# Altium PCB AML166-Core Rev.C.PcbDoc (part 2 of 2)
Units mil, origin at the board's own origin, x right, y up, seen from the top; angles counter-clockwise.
Board outline 3307.09 x 2047.24 mil, 4 copper layers (Top Layer, L2, L3, Bottom Layer), stack 30.634 mil thick; 138 components, 74 nets, 392 pads, 430 vias.
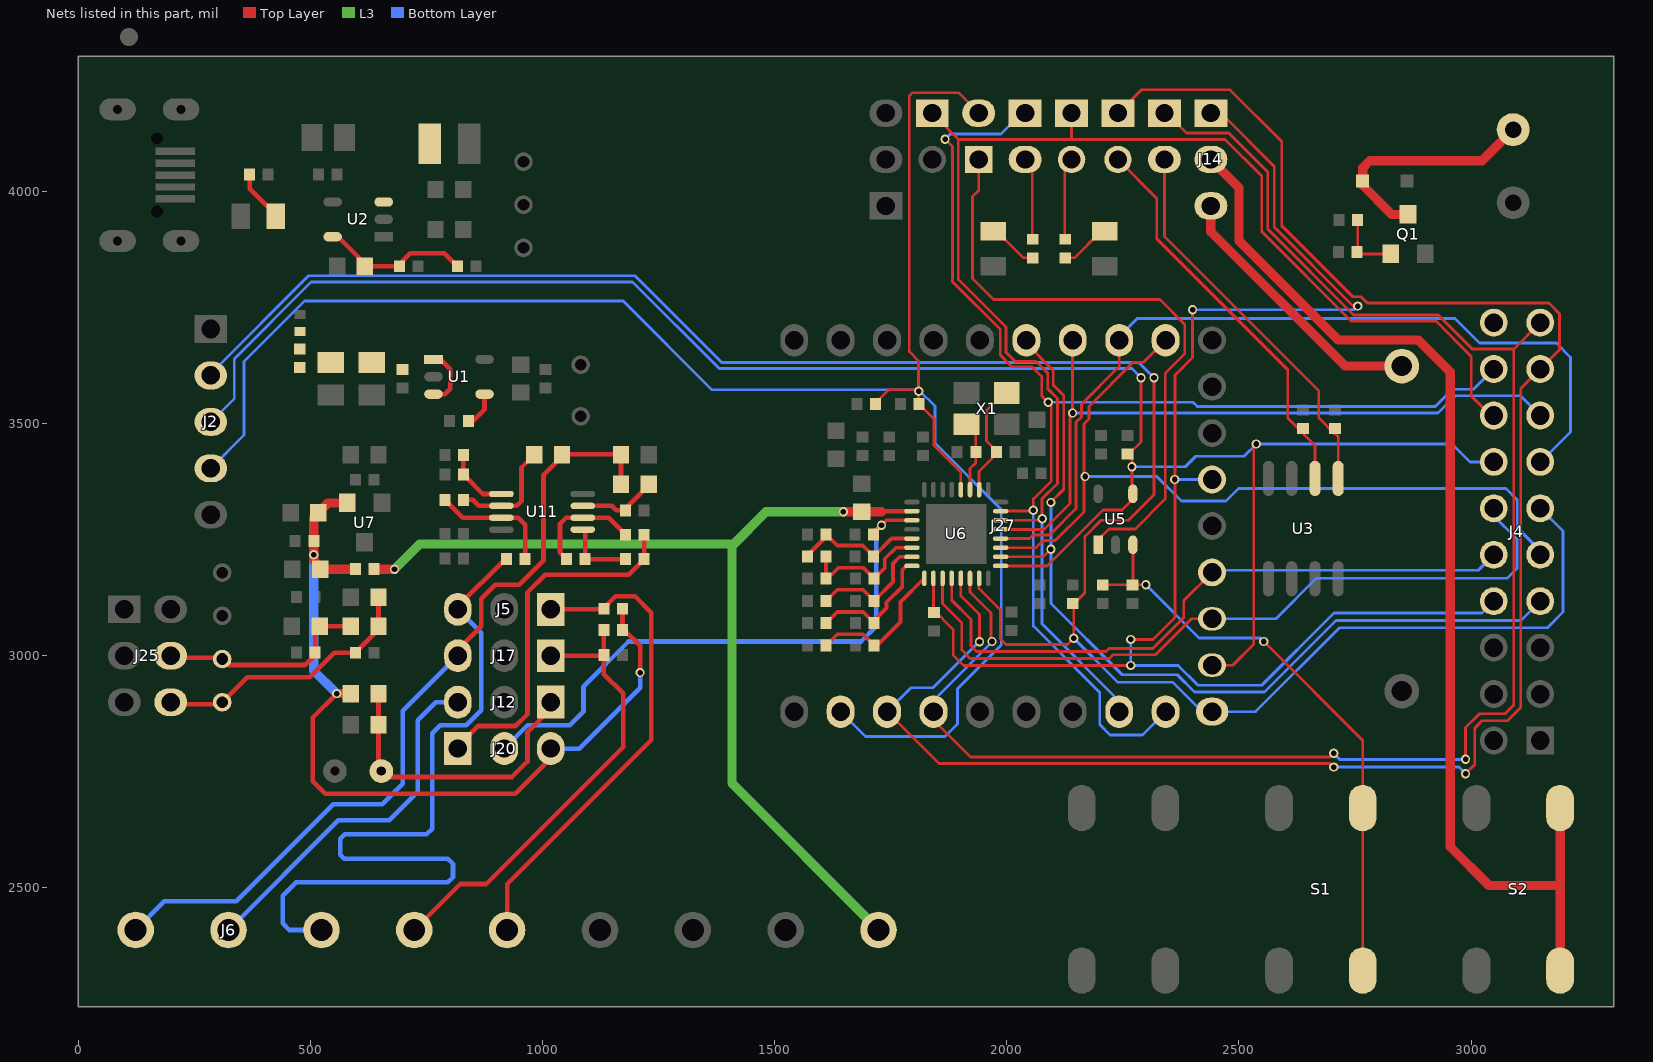
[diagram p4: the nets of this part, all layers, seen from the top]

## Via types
v1: diameter 20, hole 12, Top Layer to Bottom Layer, tented both sides, 430 vias

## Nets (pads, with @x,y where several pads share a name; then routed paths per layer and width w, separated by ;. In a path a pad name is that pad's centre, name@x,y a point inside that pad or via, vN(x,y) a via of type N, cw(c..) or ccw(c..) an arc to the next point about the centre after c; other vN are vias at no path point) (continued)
CALI_1: C41.2 Cali7.1 J25.4 R37.2 R38.2 | length 455.1
  Top Layer w10: J25.4@180,2993.11 J25.4@180,3001 ; J25.4@199,2996 306.98,2996 Cali7.1@309.87,2993.11 ; Cali7.1@322.63,2980.37 488.75,2980.37 510,3001.62 C41.2@510,3007.37 510,3064 R38.2@520,3064 R37.2@586.57,3064
CALI_2: C42.2 Cali8.1 J25.6 R33.1 R37.1 | length 582
  Top Layer w10: J25.6@199,2896 305.87,2896 Cali8.1@309.87,2900 ; Cali8.1@309.87,2901 310.87,2901 363.87,2954 498.27,2954 551,3006.73 C42.2@596.57,3006.73 R37.1@650.2,3060.36 ; R37.1@646.57,3064 R33.1@646.57,3126.37 ; R37.1@652,3059.14 R37.1@652.57,3059.71
CS/GPIO7_MINIP: J4.7 J27.22 U6.26 | length 1939.9
  Top Layer w6: U6.26@1986.56,3213.3 2078,3213.3 v1@2095,3230.3 ; J27.22@2041.98,3679.79 2041.98,3673.02 2100,3615 2100,3583.42 2122.6,3560.83 2122.6,3358.94 v1@2095,3331.34
  Bottom Layer w6: v1(2095,3330.41) v1(2095,3229.3) 2095,3113 2248.66,2959.34 2367,2959.34 2404,2922.34 2554.94,2922.34 2708.94,3076.34 3107.44,3076.34 J4.7@3148.82,3117.72
DAC/IO21_MICROP: J4.8 J14.1 J27.15 R8.2 U6.18 | length 3293.7
  Top Layer w6: U6.18@1841.87,3167.04 1841.87,3099.66 1884.41,3057.12 1884.41,3001.93 1907,2979.34 v1@2261,2979.34 ; v1(2267,3035.34) 2315,3035.34 2362,3082.34 2362,3604.44 2400,3642.44 v1@2400,3739.34 ; J14.1@2439.37,4169.09 2461,4169.09 2576,4054.09 2576,3923.34 2746,3753.34 v1(2756,3753.34)
  Bottom Layer w6: v1(2267,3035.34) v1(2267,2979.34) 2369,2979.34 2411.76,2936.58 2549.04,2936.58 2704.8,3092.34 3023.44,3092.34 J4.8@3048.82,3117.72 ; v1@2362,3379.79 J27.15@2441.98,3379.79 ; v1@2400,3739.34 2406,3745.34 2748,3745.34 v1(2756,3753.34)
  other v1: 2361.7,3379.79 2400,3745.34
GPIO11_MINIP: J2.2 J4.11 J27.10 R11.1 U6.23 | length 4649.7
  Top Layer w6: U6.23@1940.3,3167.04 1939.69,3166.43 1939.69,3145.31 1986,3099 1986,3036.59 1998.25,3024.34 2130.34,3024.34 v1(2144,3038) 2144,3112 2168,3136 2168,3257.34 2202.66,3292 2262,3292 2317,3347 v1(2317,3598.94)
  Bottom Layer w6: J2.2@290.02,3604.34 290.02,3612.59 496.07,3818.63 1199.13,3818.63 1386.02,3631.75 2284.19,3631.75 v1(2317,3598.94) ; v1(2144,3038) 2238.66,2943.34 2356.76,2943.34 2420.3,2879.79 J27.10@2441.98,2879.79 2535.4,2879.79 2715.94,3060.34 3164,3060.34 3198,3094.34 3198,3268.54 J4.11@3148.82,3317.72
GPIO14_MINIP: J2.3 J4.14 J27.11 R12.2 U5.4 U6.25 | length 4253.2
  Top Layer w6: U6.25@1986.56,3193.61 2086.28,3193.61 2207,3314.34 2248.34,3314.34 2269.49,3335.49 v1(2269.49,3407.34) R12.2@2269.49,3441.43 ; R12.2@2260,3435.02 2263.08,3435.02 R12.2@2269.49,3441.43 ; R12.2@2266,3439 2269.49,3442.49 R12.2@2269.49,3441.43 ; v1(2289,3598.94) 2289,3460.94 R12.2@2269.49,3441.43 ; J27.11@2441.98,2979.79 2486.46,2979.79 2532,3025.34 2532,3450.94 v1(2537.4,3456.34)
  Bottom Layer w6: J2.3@285.43,3503.94 336,3554.5 336,3640 501.5,3805.5 1193.69,3805.5 1380.58,3618.62 2269.32,3618.62 v1(2289,3598.94) ; v1(2269.49,3407.34) 2384.34,3407.34 2407,3430 2511.06,3430 v1(2537.4,3456.34) 2959,3456.34 2997.62,3417.72 J4.14@3048.82,3417.72
GPIO16_MINIP: J4.16 J7.1 J10.1 J27.8 U6.30 | length 3150.2
  Top Layer w6: J7.1@1842.81,4165.66 1842.81,4164.99 1895.46,4112.34 ; U6.30@1986.56,3292.04 2076,3292.04 v1(2076,3295.04) 2076,3338.37 2109,3371.37 2109,3554.34 2088,3575.34 2088,3609 2063,3634 2018,3634 1998,3654 1998,3708 1895.46,3810.54 1895.46,4112.34 ; 2139.37,4112.97 J10.1@2139.37,4169.09 ; J4.16@3049.41,3510.85 3000.39,3559.87 3000.39,3644.94 2924.24,3721.09 2741.66,3721.09 2549,3913.75 2549,4033.34 2470,4112.34 1895.46,4112.34
  Bottom Layer w6: v1@2076,3292.04 2076,3069.06 J27.8@2241.98,2903.08
GPIO18_MINIP: J4.18 J9.1 J27.9 U6.31 | length 2887.4
  Top Layer w6: v1(1867,4112.97) 1883,4096.97 1883,3805.73 1986,3702.73 1986,3647.45 2010.95,3622.5 2054.21,3622.5 2075,3601.71 2075,3560.34 v1(2089,3546.34) 2095.81,3539.53 2095.81,3376.96 2057,3338.15 v1(2057,3313.72) 2057,3311.72 U6.31@1986.56,3311.72
  Bottom Layer w6: v1(1867,4112.97) 1878.03,4124 1987.46,4124 2032.55,4169.09 J9.1@2039.37,4169.09 ; v1@2057,3311.72 2057,3064.06 2200,2921.06 2200,2852 2222.21,2829.79 2291.98,2829.79 J27.9@2341.98,2879.79 ; v1@2093,3546.34 2401,3546.34 2410.24,3537.09 2922.76,3537.09 2960,3574.34 3005.44,3574.34 J4.18@3048.82,3617.72
GPIO20_MINIP: J4.20
LED0: J9.2 R3.2 | length 155.2
  Top Layer w6: R3.2@2054.6,3898.7 J9.2@2054.6,4053.86
LED1: J10.2 R4.2 | length 155.6
  Top Layer w6: R4.2@2124.6,3898.7 J10.2@2124.6,4054.33
LM75_SCL: J4.17 J11.1 J27.3 U6.21 | length 4107.2
  Top Layer w6: J27.3@1741.98,2879.79 1853.77,2768 2696.34,2768 v1(2704,2760.34) ; U6.21@1900.93,3167.04 1900.93,3129.07 1941.08,3088.92 v1(1941.08,3030.08) ; J11.1@2246.24,4169.09 J11.1@2239.37,4169.09 2289.37,4219.09 2480.77,4219.09 2592,4107.86 2592,3926.34 2745,3773.34 2762.87,3773.34 2776.36,3759.85 3167.41,3759.85 3190.31,3736.95 3190.31,3659.21 J4.17@3148.82,3617.72 3107,3575.9 3107,2888.34 3079,2860.34 3024,2860.34 3007.71,2844.05 3007.71,2766 v1(2988,2746.29)
  Bottom Layer w6: J27.3@1741.98,2879.79 1793.52,2931.34 1841.15,2931.34 v1@1940.49,3030.67 ; v1(2704,2760.34) 2973.95,2760.34 v1(2988,2746.29)
LM75_SDA: J4.19 J13.1 J27.4 U6.22 | length 3637.8
  Top Layer w6: J27.4@1841.98,2879.79 1841.98,2861.55 1921.53,2782 2695.91,2782 v1(2704,2790.09) ; U6.22@1920.61,3167.04 1920.61,3137.41 1966.09,3091.93 v1@1966.09,3032.91 ; J13.1@2339.37,4169.09 2344.24,4169.09 2387,4126.34 2478,4126.34 2562,4042.34 2562,3919.14 2747.04,3734.09 2929.24,3734.09 3002.44,3660.9 3092,3660.9 ; v1(2988,2776.98) 2988,2845.55 3017.79,2875.34 3072.79,2875.34 3092,2894.55 3092,3660.9 ; J4.19@3148.82,3717.72 3092,3660.9
  Bottom Layer w6: J27.4@1841.98,2879.79 1841.98,2903.98 1963.67,3025.67 v1@1971.33,3025.67 ; v1(2704,2790.09) 2717.12,2776.98 v1(2988,2776.98)
  other v1: 1968,3030.84
MISO/GPIO9_MINIP: J4.9 J27.19 U6.27 | length 1775
  Top Layer w6: U6.27@1986.56,3232.98 2062.98,3232.98 2078.3,3248.3 2104.3,3248.3 2166,3310 v1@2166,3385.83 ; v1@2166,3390.84 2166,3499.14 2177,3510.14 2177,3537.34 2272,3632.34 2294.52,3632.34 J27.19@2341.98,3679.79
  Bottom Layer w6: v1(2168.5,3386.34) 2323,3386.34 2376,3333.34 2472,3333.34 2499,3360.34 3075,3360.34 3099.41,3335.93 3099.41,3275.85 3148.82,3226.44 J4.9@3148.82,3217.72
MISO/IO11_MICROP: J4.13 J27.20 U6.28 | length 1873.8
  Top Layer w6: U6.28@1986.56,3252.67 2048.76,3252.67 2056.45,3260.35 2092.35,3260.35 2149,3317 2149,3503.17 2160.6,3514.77 2160.6,3541.94 2241.98,3623.31 J27.20@2241.98,3679.79
  Bottom Layer w6: J27.20@2241.98,3679.79 2241.98,3687.31 2281,3726.34 2965.23,3726.34 3018.02,3673.55 3183.71,3673.55 3214.31,3642.95 3214.31,3482.35 3149.68,3417.72 J4.13@3148.82,3417.72
MOSI/GPIO15_MINIP: J4.15 J27.21 U6.29 | length 1565.1
  Top Layer w6: U6.29@1986.56,3272.35 2080.26,3272.35 2136,3328.09 2136,3517.49 v1(2141.6,3523.09) J27.21@2141.6,3673.81 ; J27.21@2139,3676.82 J27.21@2142.01,3673.81
  Bottom Layer w6: v1(2141.6,3523.09) 2928.56,3523.09 2965.8,3560.34 3106.2,3560.34 J4.15@3148.82,3517.72
NetBZ1_1: BZ1.1 D1.2 Q1.3 | length 519.2
  Top Layer w20: Q1.3@2864.09,3950.84 2829.12,3950.84 2766.59,4013.38 D1.2@2766.59,4022.84 2766.59,4050.95 2781.98,4066.34 3023.35,4066.34 BZ1.1@3090.55,4133.54
NetC3_1: C3.1 U1.4 | length 68.3
  Top Layer w10: C3.1@850,3505.71 875,3530.71 U1.4@875,3563.67
NetC6_1: C6.1 C15.1 C43.1 R16.2 U1.1 U1.3 | length 127.6
  Top Layer w10: U1.3@765,3563.67 789.3,3563.67 801,3575.37 801,3617.37 779.9,3638.47 U1.1@765,3638.47
NetC8_2: C8.2 R10.1 R13.2 U2.5 | length 321.2
  Top Layer w10: U2.5@547.81,3902.78 U2.5@559.07,3902.78 ; U2.5@559.37,3903.08 617.31,3845.14 R13.2@617.31,3839.18 687.18,3839.18 715,3867 788.49,3867 R10.1@816.31,3839.18
NetC9_1: C9.1 C10.1 R14.2 U6.13 | length 282
  Top Layer w8: R14.2@1610.69,3257.02 R14.2@1610.69,3261.68 1634.81,3237.56 1689.46,3237.56 C9.1@1713.09,3213.93 1751.82,3252.67 U6.13@1795.61,3252.67
  Top Layer w10: C10.1@1570.69,3217.02 R14.2@1610.69,3257.02
NetC10_2: C10.2 C11.1 R17.2 U6.14 | length 291.7
  Top Layer w8: C10.2@1610.69,3213.93 R17.2@1610.69,3166.18 1614.18,3166.18 1638,3190 1690.27,3190 C11.1@1714.09,3166.18 1737,3189.1 1737,3209 1760.98,3232.98 U6.14@1795.61,3232.98
NetC12_1: C12.1 R27.2 U6.15 | length 267.3
  Top Layer w8: R27.2@1610.69,3118.43 1634.59,3142.34 1690.34,3142.34 C12.1@1714.24,3118.43 1755,3159.19 1755,3199 1769.3,3213.3 U6.15@1795.61,3213.3
NetC21_1: C21.1 R18.2 S1.2 S1.3 U5.3 | length 1280.8
  Top Layer w6: R18.2@2206.5,3153.02 C21.1@2271,3153.02 ; U5.3@2271.49,3239.02 2271.49,3153.51 C21.1@2271,3153.02 ; v1(2299.51,3153.02) C21.1@2271,3153.02 ; v1(2553.5,3030.84) 2766.52,2817.82 S1.3@2766.52,2672.09 S1.2@2766.52,2322.09
  Bottom Layer w6: v1(2299.51,3153.02) 2414.2,3038.34 2546,3038.34 v1(2553.5,3030.84)
NetC24_1: C24.1 R28.2 U6.16 | length 287.3
  Top Layer w8: R28.2@1610.69,3070.39 1634.64,3094.34 1690.59,3094.34 C24.1@1714.24,3070.68 1714.24,3076.25 1741,3103 1741,3115.3 1775,3149.3 1775,3185.53 1783.08,3193.61 U6.16@1795.61,3193.61
NetC27_1: C27.1 R24.2 U11.6 | length 245.7
  Top Layer w10: C27.1@829.37,3335.91 850.02,3335.91 862.86,3323.07 U11.6@911.34,3323.07 944.38,3323.07 954.62,3333.31 954.62,3405.73 R24.2@981.85,3432.96
NetC27_2: C27.2 R25.1 U11.7 | length 269.4
  Top Layer w10: C27.2@789.37,3335.91 827.81,3297.48 U11.7@911.34,3297.48 947.45,3297.48 962.35,3282.58 R25.1@962.35,3208.27
NetC32_1: C32.1 R29.2 U6.17 | length 316.4
  Top Layer w8: R29.2@1610.69,3022.34 1634.68,3046.34 1690.24,3046.34 C32.1@1714.24,3022.34 1720.34,3022.34 1771,3073 1771,3115.85 U6.17@1822.19,3167.04
NetC36_1: C36.1 R30.2 U11.3 | length 173.2
  Top Layer w10: U11.3@1086.54,3323.07 1148.83,3323.07 1158.62,3313.27 C36.1@1178.94,3313.27 1178.94,3317.6 1228.94,3367.6 R30.2@1228.94,3369.27
NetC39_1: C39.1 R50.2 U11.2 | length 244.1
  Top Layer w10: C39.1@1051.76,3208.27 1037.62,3222.41 1037.62,3284.68 1050.42,3297.48 U11.2@1086.54,3297.48 1142.23,3297.48 R50.2@1178.94,3260.77
NetC39_2: C39.2 R48.1 U11.1 | length 153
  Top Layer w10: U11.1@1086.54,3271.89 1091.76,3266.66 C39.2@1091.76,3208.27 R48.1@1178.94,3208.27
NetJ14_2: J14.2 S2.2 S2.3 | length 2424.4
  Top Layer w20: J14.2@2439.37,4060.51 J14.2@2439.37,4069.09 2500,4008.46 2500,3894.34 2714,3680.34 2886,3680.34 2955,3611.34 2955,2589 3038.66,2505.34 3191.69,2505.34 ; S2.2@3191.69,2322.09 3191.69,2505.34 ; S2.3@3191.69,2672.09 3191.69,2505.34
NetJ14_3: J14.3 R7.2 | length 586.7
  Top Layer w20: J14.3@2439.37,3969.09 2439.37,3913.61 2728.89,3624.09 R7.2@2850.63,3624.09
NetL1_1: L1.1 U2.3
NetL2_1: L2.1 R16.1
NetLED0_2: LED0.2 R3.1 | length 109.4
  Top Layer w6: LED0.2@1970.63,3914.97 LED0.2@1978.03,3914.97 ; LED0.2@1978.41,3914.97 LED0.2@1978.03,3914.97 ; R3.1@2055.71,3857.29 2035.71,3857.29 LED0.2@1978.03,3914.97
NetLED1_2: LED1.2 R4.1 | length 108.9
  Top Layer w6: R4.1@2125.71,3857.29 2145.7,3857.29 2203.38,3914.97 LED1.2@2210.71,3914.97
NetLED3_1: LED3.1 R9.1 | length 112.8
  Top Layer w10: R9.1@369,4036.37 369,4006.34 425.68,3949.66 LED3.1@425.68,3947
NetQ1_1: Q1.1 R1.1 R2.2 | length 141
  Top Layer w6: R2.2@2755.69,3938.82 2755.69,3871.01 2760.85,3865.84 Q1.1@2826.69,3865.84
NetR23_2: R23.2 R31.2 U11.5 | length 145.4
  Top Layer w10: R31.2@828.85,3386.08 R31.2@829.37,3385.56 ; R23.2@829.37,3432.96 R31.2@829.37,3390.44 R31.2@829.37,3385.56 ; U11.5@911.34,3348.66 871.47,3348.66 834.57,3385.56 R31.2@829.37,3385.56
NRST_WDT: J8.1 U5.1 | length 1336.4
  Top Layer w6: J8.1@1939.37,4069.09 1939.37,4002.71 1926,3989.34 1926,3812.71 1971.37,3767.34 2330,3767.34 2383,3714.34 2383,3650.44 2341,3608.44 2341,3337.62 2276.72,3273.34 2220,3273.34 2196.68,3250.02 U5.1@2194.69,3250.02
NTC_IN: C35.2 J12.1 R15.2 RV2.2 | length 649.5
  Top Layer w10: RV2.2@646.57,2757.71 C35.2@646.57,2851.71 R15.2@646.57,2918.71 R15.2@652.57,2918.71 ; RV2.2@652.57,2751.71 665.28,2739 934,2739 967.52,2772.52 967.52,2835.52 1017.52,2885.52 J12.1@1017.52,2900.24
OSC_IN: C19.1 U6.2 X1.1 | length 253.3
  Top Layer w6: U6.2@1940.3,3357.98 1940.3,3396.95 1977.73,3434.39 C19.1@1977.73,3438.92 1977.73,3441.2 1956.39,3462.54 1956.39,3528.05 1994.05,3565.7 X1.1@1999.7,3565.7
OSC_OUT: C18.2 U6.3 X1.3 | length 126
  Top Layer w6: U6.3@1920.61,3357.98 1920.61,3403.27 1933.09,3415.74 C18.2@1933.09,3438.92 X1.3@1933.09,3478.78
PA9/UART_TX/I2C_SCL: J4.12 J27.12 U6.19 | length 1605.8
  Top Layer w6: U6.19@1861.56,3167.04 1861.56,3112.44 1903,3071 1903,3012.34 1921,2994.34 2221,2994.34 2229,3002.34 2320,3002.34 2397.46,3079.79 J27.12@2441.98,3079.79
  Bottom Layer w6: J27.12@2441.98,3079.79 2579.46,3079.79 2667,3167.34 3078,3167.34 3099,3188.34 3099,3251.26 3048.82,3301.44 J4.12@3048.82,3317.72
PA10/UART_RX/I2C_SDA: J4.10 J27.13 U6.20 | length 1401.7
  Top Layer w6: U6.20@1881.24,3167.04 1881.24,3119.76 1923.08,3077.92 1923.08,3020.92 1934.66,3009.34 2213.71,3009.34 2220.09,3015.72 2314.38,3015.72 2381,3082.34 2381,3118.82 J27.13@2441.98,3179.79
  Bottom Layer w6: J27.13@2441.98,3179.79 2446.52,3184.34 3015.44,3184.34 J4.10@3048.82,3217.72
R\E\S\E\T\: C23.1 J2.4 J8.2 J27.2 R19.2 U6.4 | length 4133.3
  Top Layer w6: R19.2@1718,3542.53 1718,3546 1745,3573 v1@1810,3573 ; C23.1@1810,3543.53 v1(1810,3570) v1@1810,3573 ; C23.1@1811,3542.53 1843,3510.53 1843,3452.82 1900.93,3394.89 U6.4@1900.93,3357.98 ; J8.2@1939.37,4169.09 1895.46,4213 1797,4213 1790,4206 1790,3655.2 1810,3635.2 v1@1810,3573
  Bottom Layer w6: J2.4@285.43,3403.94 357,3475.5 357,3634 487.37,3764.37 1173.63,3764.37 1365,3573 1810,3573 1845,3538 1845,3458.34 1988,3315.34 1988,3023 1894,2929 1894,2853.34 1867,2826.34 1695.43,2826.34 J27.2@1641.98,2879.79
REF_2.5V: C29.2 C31.1 J20.3 R15.1 R20.2 R22.1 R32.2 R43.2 U7.2 | length 1848.2
  Top Layer w10: v1(556.48,2918.71) 505,2867.23 505,2730 532.29,2702.71 941.23,2702.71 1017.52,2779 J20.3@1017.52,2800.24 ; R20.2@1172,3101.49 R43.2@1172,3055.49 1176.39,3055.49 1210,3021.88 v1(1210,2964)
  Top Layer w15: C29.2@507.16,3298.46 C29.2@517.16,3308.46 ; R32.2@516,3197 516,3187.87 R32.2@517.16,3186.71 ; R22.1@586.57,3186.71 R22.1@592.57,3186.71
  Top Layer w20: C29.2@507.16,3298.46 C31.1@507.16,3247.37 v1(507.16,3218) 507.16,3205.84 R32.2@516,3197 ; R32.2@517.16,3186.71 R32.2@521.16,3186.71 R22.1@586.57,3186.71 ; C29.2@517.16,3308.46 537.99,3329.3 U7.2@579.17,3329.3 ; v1(556.48,2918.71) R15.1@586.57,2918.71
  Bottom Layer w10: J20.3@1017.52,2800.24 1079.24,2800.24 1210.39,2931.39 v1@1210.39,2964
  Bottom Layer w20: v1(507.16,3218) 507.16,2968.03 v1(556.48,2918.71)
REF_ADC: C25.2 J20.2 U6.11 | length 1262.7
  Top Layer w8: C25.2@1714.34,3261.68 C25.2@1713.09,3261.68 1713.09,3264.43 v1(1730.01,3281.35) 1740.7,3292.04 U6.11@1795.61,3292.04
  Top Layer w10: C25.2@1713.44,3262.04 C25.2@1714.04,3262.04
  Bottom Layer w10: J20.2@917.52,2800.24 967.52,2850.24 1058.24,2850.24 1088,2880 1088,2933.74 1185.1,3030.84 1685.84,3030.84 1719,3064 1719,3270.34 v1(1730.01,3281.35)
REF_RTD: J20.1 R48.2 R50.1 | length 779.6
  Top Layer w10: J20.1@817.52,2800.24 817.52,2805.36 861.16,2849 942.16,2849 967.52,2874.36 967.52,3136.76 1005.76,3175 1185.66,3175 R48.2@1218.94,3208.27 R50.1@1218.94,3260.77
RTD_A: J5.3 J6.3 R25.2 | length 1776.7
  Top Layer w10: J5.3@817.52,3100.24 817.52,3106.56 919.23,3208.27 R25.2@922.35,3208.27
  Bottom Layer w10: J6.3@523.62,2409.45 454.55,2409.45 440,2424 440,2483 469,2512 796,2512 807,2523 807,2552 796.01,2562.99 573.01,2562.99 564,2572 564,2606 574,2616 750,2616 762,2628 762,2833 779.24,2850.24 835.2,2850.24 868,2883.04 868,3049.76 J5.3@817.52,3100.24
RTD_B: J6.2 J12.3 | length 787.4
  Bottom Layer w10: J6.2@323.62,2409.45 560.17,2646 670,2646 731,2707 731,2861 770.24,2900.24 J12.3@817.52,2900.24
RTD_C: J6.1 J17.3 R24.1 R30.1 R49.2 | length 1776.5
  Top Layer w10: J17.3@817.52,3000.24 817.52,3013.21 867.85,3063.54 867.85,3122.85 898,3153 950,3153 1001.85,3204.85 1001.85,3389.22 1046.63,3434 1167.89,3434 R49.2@1168.94,3432.96 R30.1@1168.94,3369.27
  Bottom Layer w10: J6.1@123.62,2409.45 185.51,2471.34 340.34,2471.34 549,2680 655,2680 699.15,2724.15 699.15,2881.86 J17.3@817.52,3000.24
SCL: J11.2 R6.1 U3.2 | length 862.7
  Top Layer w6: J11.2@2239.37,4069.09 2323,3985.46 2323,3898.34 2605,3616.34 2605,3512.05 2663.63,3453.42 U3.2@2663.63,3382.13
SDA: J13.2 R5.1 U3.1 | length 842.6
  Top Layer w6: J13.2@2339.37,4069.09 2339.37,3902.97 2672,3570.34 2672,3511.88 R5.1@2705.63,3478.25 ; R5.1@2706.72,3479.34 2713.63,3472.42 U3.1@2713.63,3382.13
TC_A: J3.2 J5.1 R20.1 | length 1054.4
  Top Layer w10: J3.2@923.62,2409.45 923.62,2508.62 1233.76,2818.76 1233.76,3093.24 1199,3128 1157.11,3128 1129.35,3100.24 J5.1@1017.52,3100.24
TC_B: J3.1 J17.1 R43.1 R44.1 | length 999.5
  Top Layer w10: J3.1@726.2,2409.45 J3.1@723.62,2409.45 822.8,2508.62 878.62,2508.62 1173.68,2803.68 1173.68,2919.04 1132,2960.72 R44.1@1132,3000.24 ; J17.1@1017.52,3000.24 R44.1@1132,3000.24 ; R43.1@1132,3055.49 R44.1@1132,3001.49 R44.1@1132,3000.24
VLDO: C20.1 J26.2 R22.2 U6.10 | length 2160.4
  Top Layer w9.8: 1728,3311.72 U6.10@1795.61,3311.72
  Top Layer w20: 652.57,3186.71 v1(681,3186.71) ; v1(1648,3310.27) C20.1@1687.49,3310.3 ; C20.1@1687.49,3310.3 1730,3310.3
  L3 w20: v1(681,3186.71) 735.29,3241 1407.8,3241 1407.8,3236.8 ; 1481.3,3310.3 1407.8,3236.8 ; 1481.33,3310.27 v1(1648,3310.27) ; J26.2@1723.62,2409.45 1407.8,2725.27 1407.8,3236.8
pads on no net: J1.0 J1.2 J1.3 J1.4 J27.5 J27.6 J27.7 J27.14 J27.18 J27.23 J27.24 J27.25 MARK1.0 MARK2.0 MARK3.0 U3.3

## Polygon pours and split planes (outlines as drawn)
AGND on L3 "AGND_L03_P063" (solid, remove dead copper, pour order 63): 0,2244.09 1823.62,2244.09 1823.62,2492.91 1724.2,2592.34 1477.1,2839.44 1473,2849.34 1473,2927.1 1477.1,2937 1501.26,2961.16 1511.16,2965.27 1746.15,2965.27 1803.85,3022.96 1803.85,3306.84 1856,3359 1862,3365 1862,3397 1803.84,3455.15 1803.85,3495.29 1794.8,3504.34 1334,3504.34 1133.96,3704.37 476.09,3704.37 398,3626.28 398,3278.02 393.9,3268.12 338.21,3212.44 328.32,3208.34 0,3208.34
AGND on L3 "AGND_L03_P061" (solid, remove dead copper, pour order 61): 0,3236.34 179.5,3236.34 179.5,3744.59 181.4,3749.19 277.81,3845.6 282.41,3847.5 852.34,3847.5 869.13,3864.29 869.13,4190 0,4190
3.3V on L3 "3.3V_L03_P062" (solid, remove dead copper, pour order 62): 192.5,3236.34 192.5,3741.9 285.1,3834.5 855.04,3834.5 859.63,3836.4 880.23,3857 883.41,3864.68 883.41,4190 3190,4190 3190,2244.09 1851,2244.09 1851,2505.14 1735.8,2620.34 1501,2855.14 1501,2921.3 1516.96,2937.27 1751.95,2937.27 1761.85,2941.37 1823.9,3003.41 1831,3020.56 1831,3298.69 1863.31,3331 1889,3356.69 1889,3399.85 1831,3457.85 1831,3512 1810.66,3532.34 1342.66,3532.34 1144,3731 463.12,3731 374.1,3641.98 370,3632.08 370,3283.82 322.52,3236.34
AGND on L2 "AGND_L02_P056" (solid, remove dead copper, pour order 56): 1831,3512 1831,3457.85 1883,3405.85 1883,3334 1880,3331 1843.13,3331 1831,3318.87 1831,3020.56 1823.9,3003.41 1761.85,2941.37 1751.95,2937.27 1516.96,2937.27 1501,2921.3 1501,2855.14 1735.8,2620.34 1851,2505.14 1851,2244.09 3307.09,2244.09 3307.09,4291.34 0,4291.34 0,3236.34 322.52,3236.34 370,3283.82 370,3632.08 374.1,3641.98 463.12,3731 1144,3731 1342.66,3532.34 1810.66,3532.34
AGND on L2 "AGND_L02_P055" (solid, remove dead copper, pour order 55): 0,2244.09 1823.62,2244.09 1823.62,2492.91 1724.2,2592.34 1477.1,2839.44 1473,2849.34 1473,2927.1 1477.1,2937 1501.26,2961.16 1511.16,2965.27 1746.15,2965.27 1803.85,3022.96 1803.85,3269.43 1862,3327.58 1862,3397 1803.84,3455.15 1803.85,3495.29 1794.8,3504.34 1334,3504.34 1133.96,3704.37 476.09,3704.37 398,3626.28 398,3278.02 393.9,3268.12 338.21,3212.44 328.32,3208.34 0,3208.34
AGND on Top Layer "AGND_L01_P058" (solid, remove dead copper, pour order 58): 0,2244.09 1823.62,2244.09 1823.62,2492.91 1724.2,2592.34 1477.1,2839.44 1473,2849.34 1473,2927.1 1477.1,2937 1501.26,2961.16 1511.16,2965.27 1746.15,2965.27 1803.85,3022.96 1803.85,3330.85 1832,3359 1856,3359 1862,3365 1862,3397 1803.84,3455.15 1803.85,3495.29 1794.8,3504.34 1334,3504.34 1133.96,3704.37 476.09,3704.37 398,3626.28 398,3278.02 393.9,3268.12 338.21,3212.44 328.32,3208.34 0,3208.34
AGND on Top Layer "AGND_L01_P057" (solid, remove dead copper, pour order 57): 1831,3512 1831,3457.85 1889,3399.85 1889,3343 1877,3331 1843.13,3331 1831,3318.87 1831,3020.56 1823.9,3003.41 1761.85,2941.37 1751.95,2937.27 1516.96,2937.27 1501,2921.3 1501,2855.14 1735.8,2620.34 1851,2505.14 1851,2244.09 3307.09,2244.09 3307.09,4291.34 0,4291.34 0,3236.34 322.52,3236.34 370,3283.82 370,3632.08 374.1,3641.98 463.12,3731 1144,3731 1342.66,3532.34 1810.66,3532.34
AGND on Bottom Layer "AGND_L04_P060" (solid, remove dead copper, pour order 60): 0,2244.09 1823.62,2244.09 1823.62,2492.91 1724.2,2592.34 1477.1,2839.44 1473,2849.34 1473,2927.1 1477.1,2937 1501.26,2961.16 1511.16,2965.27 1746.15,2965.27 1803.85,3022.96 1803.85,3330.85 1832,3359 1856,3359 1862,3365 1862,3397 1816,3443 1816,3483.14 1794.8,3504.34 1334,3504.34 1133.96,3704.37 476.09,3704.37 398,3626.28 398,3278.02 393.9,3268.12 338.21,3212.44 328.32,3208.34 0,3208.34
AGND on Bottom Layer "AGND_L04_P059" (solid, remove dead copper, pour order 59): 1831,3512 1831,3457.85 1910.58,3378.27 1863.31,3331 1843.13,3331 1831,3318.87 1831,3020.56 1823.9,3003.41 1761.85,2941.37 1751.95,2937.27 1516.96,2937.27 1501,2921.3 1501,2855.14 1735.8,2620.34 1851,2505.14 1851,2244.09 3307.09,2244.09 3307.09,4291.34 0,4291.34 0,3236.34 322.52,3236.34 370,3283.82 370,3632.08 374.1,3641.98 463.12,3731 1144,3731 1342.66,3532.34 1810.66,3532.34

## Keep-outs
Keep-Out Layer:
  the board outline again, w5

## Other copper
Top Layer:
  rectangle: 2764.63,3044.09 2926.63,3504.09
  rectangle: 2549.94,3220.09 2841.63,3328.09
  region net NetC6_1: 490,3632 527.76,3669.76 678.24,3669.76 774.7,3669.76 784,3660.47 784,3629.37 725.66,3629.37 702.29,3606 684.79,3606 680.79,3610 515,3610 468,3610 465.19,3612.81 465.19,3632
  region net 3.3V_6219: 901.77,3628.94 924,3606.71 1018.62,3606.71 1018.62,3638.87 992.38,3665.12 863.89,3665.11 856,3657.22 856,3635.35 862.41,3628.94
  region net NetL1_1: 640,4059.37 727.31,4146.68 780,4146.68 780,4059.71 724.34,4059.71 700,4035.37 700,3978.71 689.66,3968.37 644,3968.37 640,3972.37
  region net 3.3V: 819,4142.37 819,3900.71 830,3889.71 905.34,3889.71 912,3896.37 912,3939.66 880,3971.66 865,3986.67 865,4142.37
  region net 5V: 198,4079.8 446.01,4079.8 462,4063.82 462,4019 513.18,3967.82 558,3967.82 558,3987.04 525,4020.04 525,4142.01 522.01,4145 480.66,4145 466.66,4131 234.05,4131 197,4093.94 197,4080
  region net AGND: 550,4143.47 550,4018.37 580,3988.37 580,3947.28 596.57,3930.71 682.66,3930.71 691,3922.37 691,3898.71 698.11,3891.59 786.05,3891.59 786.05,4022.09 720,4022.09 720,3975.37 694,3949.37 631,3949.37 626,3954.37 626,4063.37 679,4116.37 679,4139 674.53,4143.47
  region net NetL2_1: 463.91,3709 458.85,3703.94 458.85,3654.15 463,3650 489.51,3650 495,3655.49 495,3705 491,3709
L2:
  region net AGND: 1891.09,3331 1785.69,3331 1785.69,3197.52 1891.09,3197.52
Bottom Layer:
  pour cut-out: 2489.8,4213.62 2489.8,4068 1739.37,4068 1739.37,4213.62 1788.94,4213.62

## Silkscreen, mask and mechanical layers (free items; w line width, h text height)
Top Overlay:
  region: 3387.82,4420.4 3387.82,4408.4 3242.82,4408.4 3242.82,4381.4 3387.82,4381.4 3387.82,4370.4 3449.82,4395.4
  lines w8: 3242.82,4381.4 3242.82,4408.4 3387.82,4408.4 3387.82,4420.4 3449.82,4395.4 3387.82,4370.4 3387.82,4381.4 3242.82,4381.4
  text "POWER" at 24,4224 h60
  text "3.3VA" at 1555,4149.09 h30
  text "PA8" at 2505,4139.09 h30
  text "Vmic" at 1570,4059.09 h30
  text "5V" at 1004,4052 h40
  text "KEY" at 2505,4049.09 h30
  text "GND" at 1004,3958.9 h40
  text "5V" at 1610,3954.09 h30
  text "RES" at 2505,3949.09 h30
  text "AML166-Core" at 1144.35,3885.54 h50
  text "3.3VD" at 1004,3865.81 h40
  text "PWR" at 329.85,3848 h60
  text "190114 Rev.C" at 1236.95,3830.64 h30
  text "P/N:13.01.04104" at 1210.24,3773.69 h30
  text "3.3V" at 69.78,3724.01 h36
  text "SWDIO" at 54.78,3624.01 h36
  text "3.3VA" at 1126,3615 h40
  text "SWCLK" at 44.78,3524.01 h36
  text "GND" at 1136.98,3503.17 h40
  text "RST" at 76.66,3424.01 h36
  text "GND" at 74.78,3324.01 h36
  text "GND" at 347.03,3167 h40
  text "Cal0" at 348.97,3076 h40
  text "Cal1" at 351,2980 h40
  text "Cal2" at 348.99,2884 h40
  text "MicroPort" at 1491.98,2723 h50
  text "RTDB" at 324.71,2626.92 h45
  text "RTDA" at 482.31,2626.92 h45
  text "RTDC" at 167.11,2626.45 h45
  text "TC-" at 763.31,2626.45 h45
  text "TC+" at 895.41,2626.45 h45
  text "Br+" at 1171,2626.45 h45
  text "Br-" at 1302.16,2626.45 h45
  text "GND" at 1555.41,2626.45 h45
  text "VCC" at 1693.41,2626.45 h45
  text "RST" at 2519.41,2451.35 h36 r90
  text "BOOT0" at 2094,2417.42 h36 r90
  text "KEY/RES" at 2941.41,2393.85 h36 r90
Bottom Overlay:
  lines w5: 47,2688 251,2688 251,3153 47,3153 47,2688 ; 752.85,2735.89 1080,2735.89 1080,3360 752.85,3360 752.85,2735.89
  text "PB6" at 1869.99,4232.34 h45
  text "RST" at 1978,4232 h45
  text "PB7" at 2076,4232.09 h45
  text "PB6" at 2176,4232.09 h45
  text "PA11" at 2280.36,4232.09 h45
  text "PA12" at 2385,4232 h45
  text "3.3V" at 1672,4150.09 h45
  text "PA8" at 2589,4149.09 h45
  text "Vmic" at 1672,4060.09 h45
  text "KEY" at 2584,4059.09 h45
  text "BEEP" at 1894,3974.57 h40
  text "nRST" at 2002,3974.09 h40
  text "LED0" at 2107,3974.44 h40
  text "LED1" at 2209,3974.44 h40
  text "SCL" at 2297,3974.09 h40
  text "SDA" at 2389,3974.09 h40
  text "RES" at 2584,3959.09 h45
  text "5V" at 1672,3955.09 h45
  text "NC" at 2995,3704.09 h45
  text "PA12" at 3291,3704.09 h45
  text "VREF" at 2597,3666.55 h45
  text "PB7" at 2995,3604.09 h45
  text "PA11" at 3291,3604.09 h45
  text "PA1" at 2594,3566.55 h45
  text "NC" at 1727.09,3541.79 h45 r270
  text "NC" at 1827.09,3541.79 h45 r270
  text "NC" at 1927.09,3541.79 h45 r270
  text "PB5" at 2127.09,3531.29 h45 r270
  text "PB4" at 2227.09,3531.16 h45 r270
  text "PB3" at 2327.09,3531.54 h45 r270
  text "3.3V" at 1627.09,3527.73 h45 r270
  text "PA15" at 2027.09,3520.09 h45 r270
  text "PB6" at 2995,3504.09 h45
  text "PB5" at 3291,3504.09 h45
  text "PA0" at 2594,3466.55 h45
  text "5V/3.3VA" at 1530,3440.09 h45 r270
  text "PA14" at 2995,3404.09 h45
  text "PB4" at 3291,3404.09 h45
  text "PA8" at 2594,3366.55 h45
  text "RTA" at 854.94,3308.39 h45
  text "A13" at 953.08,3308.39 h45
  text "TCA" at 1056.94,3308.39 h45
  text "TXD/PA9" at 2996,3304.09 h45
  text "PA13" at 3291,3304.09 h45
  text "NC" at 2594,3266.55 h45
  text "RTC" at 853.97,3258.01 h45
  text "A14" at 953.47,3258.01 h45
  text "TCB" at 1056.02,3258.01 h45
  text "RTB" at 854.02,3207.62 h45
  text "A12" at 952.93,3207.62 h45
  text "NTC" at 1054.95,3207.62 h45
  text "RXD/PA10" at 2996,3204.09 h45
  text "PB3" at 3291,3204.09 h45
  text "PA10" at 2594,3166.55 h45
  text "RE1" at 849.52,3157.24 h45
  text "REF" at 954.84,3157.24 h45
  text "RE2" at 1052.76,3157.24 h45
  text "PA8" at 2996,3104.09 h45
  text "PA15" at 3291,3104.09 h45
  text "PA9" at 2594,3066.55 h45
  text "PA0" at 3291,3004.09 h45
  text "PA1" at 2996,3003.09 h45
  text "PA14" at 2594,2966.55 h45
  text "GND" at 1527.86,2939.09 h45 r270
  text "RST" at 1628.09,2939.09 h45 r270
  text "PA11" at 1728.09,2939.09 h45 r270
  text "PA12" at 1828.09,2939.09 h45 r270
  text "NC" at 1928.09,2939.09 h45 r270
  text "NC" at 2028.09,2939.09 h45 r270
  text "NC" at 2128.09,2939.09 h45 r270
  text "PB6/TXD" at 2227.09,2939.09 h45 r270
  text "PB7/RXD" at 2328,2939.09 h45 r270
  text "GND" at 3291,2904.09 h45
  text "GND" at 2996,2903.09 h45
  text "PA13" at 2594,2866.55 h45
  text "5V" at 2994,2804.09 h45
  text "3.3V" at 3291,2804.09 h45
  text "A12" at 132,2801.94 h40
  text "Cal0" at 230,2802 h40
  text "A13" at 132.13,2755.65 h40
  text "Cal1" at 227.97,2755.5 h40
  text "A12" at 132,2708.94 h40
  text "Cal2" at 229.98,2709 h40
  text "RTDC" at 176,2466.45 h45
  text "RTDB" at 375,2466.45 h45
  text "RTDA" at 578,2466.45 h45
  text "TC-" at 757,2466.45 h45
  text "TC+" at 962.57,2466.45 h45
  text "Br+" at 1158,2466.45 h45
  text "Br-" at 1350,2466.45 h45
  text "GND" at 1565,2466.45 h45
  text "VCC" at 1763.57,2466.45 h45
Mechanical 1:
  lines w0.5: 0,196.85 0,0 6692.91,0 6692.91,196.85 ; 0,4291.34 0,4488.19 6692.91,4488.19 6692.91,4291.34
  lines w5: 6752.74,160.76 6716.74,196.76 ; 6752.74,232.76 6716.74,196.76 ; 6752.74,2208 6716.74,2244 ; 6752.74,2280 6716.74,2244 ; 6752.74,4255.24 6716.74,4291.24 ; 6752.74,4327.24 6716.74,4291.24 ; 6970.74,196.76 6716.74,196.76 ; 6970.74,2244 6716.74,2244 ; 6970.74,4291.24 6716.74,4291.24 ; 0,2244.09 0,196.85 3307.09,196.85 ; 0,2244.09 0,4291.34 3307.09,4291.34 ; 0,2244.09 3307.09,2244.09 ; 3307.09,196.85 3307.09,2244.09 ; 3307.09,196.85 3385.83,196.85 ; 3307.09,2244.09 3307.09,4291.34 ; 3307.09,2244.09 3385.83,2244.09 ; 3307.09,4291.34 3385.83,4291.34 ; 3385.83,196.85 6692.91,196.85 6692.91,2244.09 ; 3385.83,196.85 3385.83,2244.09 ; 3385.83,2244.09 6692.91,2244.09 ; 3385.83,2244.09 3385.83,4291.34 ; 3385.83,4291.34 6692.91,4291.34 6692.91,2244.09
  text "VCUT" at 7012.74,4262.24 h60
  text "挖空" at 3365,3251 h60 r90
  text "F" at 5015.74,3072 h500
  text "F" at 1582,3041.34 h500
  text "VCUT" at 7012.74,2215 h60
  text "挖空" at 3367,1331 h60 r90
  text "F" at 1582,961.85 h500
  text "F" at 5007.74,961.85 h500
  text "VCUT" at 7012.74,167.76 h60
Mechanical 2:
  drawing of 662 lines, arcs and shapes, not listed
  text "PCB加工工艺要求" at -5065.59,4524.76 h280
  text "mm x" at -5868.59,4338.76 h100
  text "mm" at -5258.59,4338.76 h100
  text "170" at -6203.59,4329.76 h100
  text "114" at -5593.59,4329.76 h100
  text "IPC-600E   IPC-6011/12" at -4100.59,4328.76 h100
  text "IPC-Ⅱ" at -2765.59,4327.76 h100
  text "IPC-Ⅲ" at -2265.59,4327.76 h100
  text "尺寸" at -6756.89,4310.91 h150
  text "验收标准" at -4756.89,4310.91 h150
  text "FR4 TG140" at -6050.59,4128.76 h100
  text "FR4 TG170" at -5150.59,4128.76 h100
  text "生益有胶材料" at -4250.59,4128.76 h100
  text "MEGTRON6" at -3350.59,4128.76 h100
  text "其他：" at -2450.59,4128.76 h100
  text "板材" at -6758.32,4110.69 h150
  text "单面" at -6050.59,3928.76 h100
  text "2" at -5350.59,3928.76 h100
  text "4" at -4650.59,3928.76 h100
  text "6" at -3950.59,3928.76 h100
  text "8" at -3250.59,3928.76 h100
  text "10" at -2550.59,3928.76 h100
  text "板层" at -6758.32,3910.48 h150
  text "0.4mm" at -6050.59,3728.76 h100
  text "0.6mm" at -5500.59,3728.76 h100
  text "0.8mm" at -4950.59,3728.76 h100
  text "1.0mm" at -4400.59,3728.76 h100
  text "1.2mm" at -3850.59,3728.76 h100
  text "1.4mm" at -3300.59,3728.76 h100
  text "1.6mm" at -2750.59,3728.76 h100
  text "1.8mm" at -2200.59,3728.76 h100
  text "2.0mm" at -1650.59,3728.76 h100
  text "板厚" at -6758.32,3710.26 h150
  text "1/2OZ" at -4820.59,3528.76 h100
  text "1OZ" at -4320.59,3528.76 h100
  text "2OZ" at -3820.59,3528.76 h100
  text "1/2OZ" at -2789,3528.76 h100
  text "1OZ" at -2289,3528.76 h100
  text "2OZ" at -1789,3528.76 h100
  text "（完成铜厚）" at -5817.29,3516.01 h130
  text "外层" at -6093.54,3509.76 h150
  text "内层" at -3435.95,3509.76 h150
  text "铜厚" at -6758.46,3508.48 h150
  text "白色" at -5600.59,3328.76 h100
  text "其他：" at -4900.59,3328.76 h100
  text "丝印颜色" at -6758.46,3309.26 h150
  text "绿色" at -5600.59,3128.76 h100
  text "黑色" at -4900.59,3128.76 h100
  text "红色" at -4200.59,3128.76 h100
  text "蓝色" at -3500.59,3128.76 h100
  text "黄色" at -2800.59,3128.76 h100
  text "其他：" at -2100.59,3128.76 h100
  text "（亮光）" at -6218.09,3116.16 h130
  text "阻焊颜色" at -6758.46,3109.05 h150
  text "沉镍金" at -5600.59,2928.76 h100
  text "无铅喷锡" at -4900.59,2928.76 h100
  text "电镀镍金" at -4200.59,2928.76 h100
  text "电镀软金" at -3500.59,2928.76 h100
  text "化学沉锡" at -2800.59,2928.76 h100
  text "光板" at -2100.59,2928.76 h100
  text "OSP" at -1580.59,2928.76 h100
  text "表面处理工艺" at -6758.46,2907.84 h150
  text "无" at -5600.59,2729.76 h100
  text "按键镀硬金" at -5180.59,2729.76 h100
  text "金手指" at -4460.59,2729.76 h100
  text "半孔工艺" at -3770.59,2729.76 h100
  text "FPCB补强" at -3080.59,2729.76 h100
  text "树脂塞孔" at -2390.59,2729.76 h100
  text "电镀填孔" at -1700.59,2729.76 h100
  text "特殊工艺" at -6758.46,2708.62 h150
  text "是" at -5600.59,2528.76 h100
  text "否" at -4900.59,2528.76 h100
  text "按文件" at -4200.59,2528.76 h100
  text "是否阻焊塞孔" at -6758.32,2507.98 h150
  text "非拼板" at -5600.59,2328.76 h100
  text "拼板" at -4900.59,2328.76 h100
  text "分成单板交货" at -4200.59,2328.76 h100
  text "交货方式" at -6758.46,2308.76 h150
  text "Gerber输出：英制、相对零点、抑制前导零、精度2:5" at -6755.59,2134.76 h120
  text "Ver 18.04.19" at -2060.59,2067.76 h120
  text "NC Drill输出：英制、相对零点、抑制前导零、精度2:4" at -6755.59,1994.76 h120
  text "R" at -1709.59,1865.26 h25
  text "其他说明" at -6760.59,1819.76 h150
  text "94V-0" at -1639.59,1809.76 h46
  text "标识样式>>>" at -2500.59,1754.76 h120
  text "CTI>=175" at -1795.59,1724.76 h86.61
  text "1." at -6785.59,1684.76 h120
  text "机械1层(*.GM1)为外形铣边；若存在工艺副边，请在副边上增加分流点" at -6660.59,1684.76 h120
  text "2." at -6785.7,1554.76 h120
  text "请用供应商UL认证号，防火等级，CTI等级，生产周期替换放置在板上的UR标识，且保持其位置、方向一致；" at -6660.59,1554.76 h120
  text "禁止添加板内不存在的标识，包括供应商LOGO、无铅等。但工艺副边不受限" at -6660.59,1424.76 h120
  text "3." at -6785.59,1294.76 h120
  text "若焊盘开窗与丝印油冲突，焊盘处需将丝印油掏开，不允许上盘" at -6660.59,1294.76 h120
  text "4." at -6785.59,1174.76 h120
  text "若存在V-CUT，无特别说明时，须为双面V-CUT，角度30（+-5°），余量按以下表格执行" at -6660.59,1174.76 h120
  text "PCB厚度（mm）" at -6229.59,999.76 h120
  text "筋厚" at -6564.59,984.76 h120
  text "（余量）" at -6614.59,864.76 h120
  text "0.6" at -6229.59,859.76 h120
  text "0.8" at -5989.97,859.76 h120
  text "1" at -5693.67,859.76 h120
  text "1.2" at -5509.59,859.76 h120
  text "1.6" at -5269.59,859.76 h120
  text "2" at -4984.59,859.76 h120
  text "2.5" at -4790.2,859.76 h120
  text "3" at -4504.59,859.76 h120
  text "0.16" at -6259.45,722.26 h120
  text "0.2" at -5989.45,722.26 h120
  text "0.3" at -5749.45,722.26 h120
  text "0.3" at -5513.59,722.26 h120
  text "0.4" at -5273.07,722.26 h120
  text "0.5" at -5029.3,722.26 h120
  text "0.5" at -4789.45,722.26 h120
  text "最小值" at -6619.59,719.76 h120
  text "0.5" at -4550.59,719.76 h120
  text "0.32" at -6259.05,584.76 h120
  text "0.4" at -5989.74,584.76 h120
  text "0.45" at -5779.6,584.76 h120
  text "0.5" at -5513.87,584.76 h120
  text "0.6" at -5270.59,584.76 h120
  text "0.7" at -5029.01,584.76 h120
  text "0.8" at -4789.28,584.76 h120
  text "0.8" at -4549.47,584.76 h120
  text "最大值" at -6619.59,579.76 h120
  text "5." at -6785.59,409.76 h120
  text "PCB做完后，请高温烘烤进行应力释放，再整平（或重物压板烘烤），防止翘曲" at -6660.59,409.76 h120
  text "我司生产使用无铅工艺制程" at -6665.59,274.76 h120
  text "6." at -6785.59,269.76 h120
  text "7." at -6785.59,124.76 h120
  text "未尽事项请参照我司《PCB质量补充协议》" at -6665.59,124.76 h120
Drill Drawing:
  text ".Legend" at 7744.41,155.85 h60

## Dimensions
0,4488.19 to 0,0 on Mechanical 1
0,4488.19 to 6692.91,4488.19 on Mechanical 1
